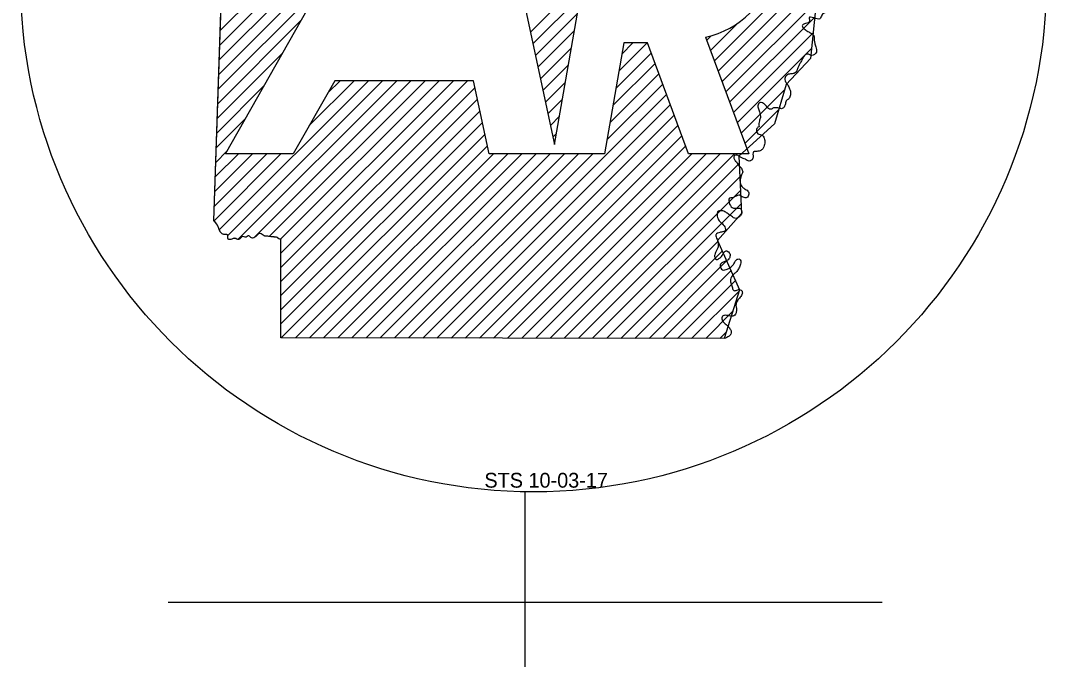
# Model space of a CAD drawing. Extents: x 1373094 to 1376427, y 1168361 to 1170494.
# Drawn here: x 1374019.33 to 1374059.68, y 1169704 to 1169729.15 of the extents above; entities that cross this region are included whole.
import ezdxf

# ---------------------------------------------------------------- set-up
doc = ezdxf.new("R2010")
doc.units = 0
doc.layers.add('R_Draft', color=7, linetype='Continuous')
doc.layers.add('R_Water Annot', color=7, linetype='Continuous')

msp = doc.modelspace()

# ---------------------------------------------------------------- linework, layer by layer
at = {"layer": 'R_Draft'}
for p, q in [((1374027.385, 1169723.893), (1374035.162, 1169737.628)), ((1374043.988, 1169728.261), (1374043.052, 1169728.261)), ((1374045.602, 1169723.893), (1374043.988, 1169728.261)), ((1374046.274, 1169728.495), (1374047.974, 1169723.893)), ((1374031.686, 1169726.775), (1374030.054, 1169723.893)), ((1374037.148, 1169726.775), (1374031.686, 1169726.775)), ((1374030.054, 1169723.893), (1374027.385, 1169723.893)), ((1374042.291, 1169723.893), (1374037.765, 1169723.893)), ((1374047.974, 1169723.893), (1374045.602, 1169723.893)), ((1374039.178, 1169659.407), (1374039.178, 1169710.597)), ((1374025.136, 1169706.246), (1374053.217, 1169706.246))]:
    msp.add_line(p, q, dxfattribs=at)
for points in [[(1374026.933, 1169721.272), (1374027.361, 1169734.176), (1374026.377, 1169742.081)], [(1374054.888, 1169738.766), (1374055.553, 1169738.071), (1374053.894, 1169736.707), (1374054.073, 1169735.33), (1374052.65, 1169734.392), (1374053.137, 1169732.274), (1374052.04, 1169731.274), (1374051.942, 1169730.185), (1374050.608, 1169729.705), (1374050.401, 1169727.653), (1374049.442, 1169726.626), (1374048.979, 1169725.08), (1374047.583, 1169723.803), (1374047.689, 1169721.548), (1374046.74, 1169720.485), (1374047.604, 1169718.551), (1374047.006, 1169716.629)], [(1374037.473, 1169737.628), (1374040.334, 1169724.261), (1374042.164, 1169734.763)], [(1374026.935, 1169721.27), (1374027.227, 1169730.125)], [(1374043.052, 1169728.261), (1374042.291, 1169723.893)], [(1374037.765, 1169723.893), (1374037.148, 1169726.775)], [(1374047.006, 1169716.629), (1374029.573, 1169716.658), (1374029.564, 1169720.506)], [(1374047.005, 1169716.627), (1374029.573, 1169716.658), (1374029.566, 1169720.507)]]:
    msp.add_lwpolyline(points, dxfattribs=at)
msp.add_ellipse((1374039.504, 1169730.77), major_axis=(20.176, 0), ratio=0.999976, dxfattribs=at)
msp.add_ellipse((1374045.557, 1169731.909), major_axis=(-3.489, 0), ratio=0.999987, start_param=1.777838, end_param=4.099264, dxfattribs=at)
for points in [[(1374051.01, 1169729.476), (1374050.845, 1169729.35), (1374050.77, 1169729.218), (1374050.347, 1169729.256), (1374050.358, 1169729.108), (1374050.208, 1169729.03), (1374050.074, 1169728.933), (1374050.15, 1169728.818), (1374050.294, 1169728.714), (1374050.436, 1169728.634), (1374050.525, 1169728.554), (1374050.549, 1169728.355), (1374050.575, 1169728.233), (1374050.622, 1169728.06), (1374050.64, 1169727.944), (1374050.554, 1169727.803), (1374050.454, 1169727.772), (1374050.351, 1169727.806), (1374050.228, 1169727.815), (1374050.128, 1169727.722), (1374050.056, 1169727.587), (1374049.986, 1169727.451), (1374049.932, 1169727.339), (1374049.876, 1169727.214), (1374049.776, 1169727.07), (1374049.649, 1169727.05), (1374049.495, 1169727.011), (1374049.404, 1169726.909), (1374049.42, 1169726.731), (1374049.505, 1169726.613), (1374049.571, 1169726.463), (1374049.616, 1169726.336), (1374049.597, 1169726.175), (1374049.53, 1169726.053), (1374049.443, 1169725.982), (1374049.404, 1169725.832), (1374049.341, 1169725.715), (1374049.286, 1169725.68), (1374049.172, 1169725.691), (1374049.049, 1169725.713), (1374048.944, 1169725.704), (1374048.845, 1169725.651), (1374048.743, 1169725.685), (1374048.639, 1169725.798), (1374048.553, 1169725.884), (1374048.457, 1169725.918), (1374048.355, 1169725.866), (1374048.341, 1169725.707), (1374048.389, 1169725.548), (1374048.43, 1169725.327), (1374048.389, 1169725.196), (1374048.374, 1169724.973)], [(1374048.374, 1169724.973), (1374048.361, 1169724.967), (1374048.277, 1169724.86), (1374048.323, 1169724.691), (1374048.509, 1169724.626), (1374048.594, 1169724.465), (1374048.598, 1169724.323), (1374048.539, 1169724.127), (1374048.451, 1169724.035), (1374048.286, 1169723.996), (1374048.159, 1169723.974), (1374048.14, 1169723.755), (1374048.08, 1169723.646), (1374047.982, 1169723.613), (1374047.838, 1169723.683), (1374047.752, 1169723.72), (1374047.648, 1169723.767), (1374047.515, 1169723.842), (1374047.413, 1169723.829), (1374047.442, 1169723.622), (1374047.452, 1169723.613), (1374047.567, 1169723.455), (1374047.679, 1169723.331), (1374047.732, 1169723.184)], [(1374048.374, 1169724.973), (1374048.361, 1169724.967), (1374048.277, 1169724.86), (1374048.323, 1169724.691), (1374048.509, 1169724.626), (1374048.594, 1169724.465), (1374048.598, 1169724.323), (1374048.539, 1169724.127), (1374048.451, 1169724.035), (1374048.286, 1169723.996), (1374048.159, 1169723.974), (1374048.14, 1169723.755), (1374048.08, 1169723.646), (1374047.982, 1169723.613), (1374047.838, 1169723.683), (1374047.752, 1169723.72), (1374047.648, 1169723.767), (1374047.515, 1169723.842), (1374047.413, 1169723.829), (1374047.442, 1169723.622), (1374047.452, 1169723.613), (1374047.567, 1169723.455), (1374047.679, 1169723.331), (1374047.732, 1169723.184)], [(1374047.732, 1169723.184), (1374047.687, 1169723.073), (1374047.632, 1169722.884), (1374047.648, 1169722.724), (1374047.721, 1169722.586), (1374047.833, 1169722.51), (1374047.959, 1169722.401), (1374047.948, 1169722.232), (1374047.875, 1169722.173), (1374047.707, 1169722.212), (1374047.579, 1169722.273), (1374047.472, 1169722.238), (1374047.327, 1169722.167), (1374047.215, 1169722.148), (1374047.22, 1169721.922), (1374047.365, 1169721.761), (1374047.494, 1169721.761), (1374047.645, 1169721.743), (1374047.696, 1169721.572), (1374047.609, 1169721.427), (1374047.468, 1169721.358), (1374047.287, 1169721.445), (1374047.159, 1169721.534), (1374047.03, 1169721.619), (1374046.869, 1169721.661), (1374046.777, 1169721.644), (1374046.734, 1169721.445), (1374046.811, 1169721.263), (1374046.933, 1169721.137), (1374047.047, 1169720.978), (1374047.03, 1169720.856), (1374046.944, 1169720.825), (1374046.791, 1169720.791), (1374046.702, 1169720.745), (1374046.679, 1169720.707), (1374046.726, 1169720.544), (1374046.767, 1169720.37), (1374046.767, 1169720.233), (1374046.715, 1169720.114), (1374046.634, 1169719.924), (1374046.644, 1169719.801), (1374046.702, 1169719.74), (1374046.772, 1169719.759), (1374046.869, 1169719.825), (1374046.93, 1169719.902), (1374046.984, 1169719.998), (1374047.081, 1169720.077), (1374047.204, 1169720.006), (1374047.233, 1169719.859), (1374047.162, 1169719.732), (1374047.062, 1169719.672), (1374046.941, 1169719.624), (1374046.849, 1169719.522), (1374046.871, 1169719.396), (1374046.944, 1169719.33), (1374047.122, 1169719.365), (1374047.237, 1169719.418), (1374047.307, 1169719.48), (1374047.387, 1169719.563), (1374047.427, 1169719.647), (1374047.491, 1169719.732), (1374047.602, 1169719.755), (1374047.654, 1169719.685), (1374047.632, 1169719.522), (1374047.567, 1169719.367), (1374047.475, 1169719.241), (1374047.377, 1169719.152), (1374047.253, 1169718.956), (1374047.278, 1169718.776), (1374047.327, 1169718.624), (1374047.388, 1169718.513), (1374047.505, 1169718.536), (1374047.632, 1169718.551), (1374047.707, 1169718.49), (1374047.701, 1169718.356), (1374047.606, 1169718.224), (1374047.515, 1169718.103), (1374047.468, 1169717.934), (1374047.487, 1169717.812), (1374047.487, 1169717.707), (1374047.449, 1169717.584), (1374047.383, 1169717.518), (1374047.204, 1169717.52), (1374047.02, 1169717.541), (1374046.921, 1169717.485), (1374046.941, 1169717.324), (1374047.047, 1169717.204), (1374047.123, 1169717.144), (1374047.233, 1169717.01), (1374047.281, 1169716.901), (1374047.267, 1169716.805), (1374047.198, 1169716.721), (1374047.005, 1169716.627)], [(1374047.732, 1169723.184), (1374047.687, 1169723.073), (1374047.632, 1169722.884), (1374047.648, 1169722.724), (1374047.721, 1169722.586), (1374047.833, 1169722.51), (1374047.959, 1169722.401), (1374047.948, 1169722.232), (1374047.875, 1169722.173), (1374047.707, 1169722.212), (1374047.579, 1169722.273), (1374047.472, 1169722.238), (1374047.327, 1169722.167), (1374047.215, 1169722.148), (1374047.22, 1169721.922), (1374047.365, 1169721.761), (1374047.494, 1169721.761), (1374047.645, 1169721.743), (1374047.696, 1169721.572), (1374047.609, 1169721.427), (1374047.468, 1169721.358), (1374047.287, 1169721.445), (1374047.159, 1169721.534), (1374047.03, 1169721.619), (1374046.869, 1169721.661), (1374046.777, 1169721.644), (1374046.734, 1169721.445), (1374046.811, 1169721.263), (1374046.933, 1169721.137), (1374047.047, 1169720.978), (1374047.03, 1169720.856), (1374046.944, 1169720.825), (1374046.791, 1169720.791), (1374046.702, 1169720.745), (1374046.679, 1169720.707), (1374046.726, 1169720.544), (1374046.767, 1169720.37), (1374046.767, 1169720.233), (1374046.715, 1169720.114), (1374046.634, 1169719.924), (1374046.644, 1169719.801), (1374046.702, 1169719.74), (1374046.772, 1169719.759), (1374046.869, 1169719.825), (1374046.93, 1169719.902), (1374046.984, 1169719.998), (1374047.081, 1169720.077), (1374047.204, 1169720.006), (1374047.233, 1169719.859), (1374047.162, 1169719.732), (1374047.062, 1169719.672), (1374046.941, 1169719.624), (1374046.849, 1169719.522), (1374046.871, 1169719.396), (1374046.944, 1169719.33), (1374047.122, 1169719.365), (1374047.237, 1169719.418), (1374047.307, 1169719.48), (1374047.387, 1169719.563), (1374047.427, 1169719.647), (1374047.491, 1169719.732), (1374047.602, 1169719.755), (1374047.654, 1169719.685), (1374047.632, 1169719.522), (1374047.567, 1169719.367), (1374047.475, 1169719.241), (1374047.377, 1169719.152), (1374047.253, 1169718.956), (1374047.278, 1169718.776), (1374047.327, 1169718.624), (1374047.388, 1169718.513), (1374047.505, 1169718.536), (1374047.632, 1169718.551), (1374047.707, 1169718.49), (1374047.701, 1169718.356), (1374047.606, 1169718.224), (1374047.515, 1169718.103), (1374047.468, 1169717.934), (1374047.487, 1169717.812), (1374047.487, 1169717.707), (1374047.449, 1169717.584), (1374047.383, 1169717.518), (1374047.204, 1169717.52), (1374047.02, 1169717.541), (1374046.921, 1169717.485), (1374046.941, 1169717.324), (1374047.047, 1169717.204), (1374047.123, 1169717.144), (1374047.233, 1169717.01), (1374047.281, 1169716.901), (1374047.267, 1169716.805), (1374047.198, 1169716.721), (1374047.005, 1169716.627)], [(1374029.564, 1169720.506), (1374029.583, 1169720.496), (1374029.492, 1169720.558), (1374029.369, 1169720.62), (1374029.231, 1169720.63), (1374029.055, 1169720.653), (1374028.907, 1169720.668), (1374028.755, 1169720.767), (1374028.593, 1169720.663), (1374028.413, 1169720.587), (1374028.308, 1169720.672), (1374028.17, 1169720.615), (1374028.075, 1169720.644), (1374027.908, 1169720.53), (1374027.751, 1169720.572), (1374027.637, 1169720.539), (1374027.495, 1169720.544), (1374027.466, 1169720.706), (1374027.328, 1169720.729), (1374027.209, 1169720.796), (1374027.128, 1169720.963), (1374027.071, 1169721.091), (1374026.933, 1169721.272)], [(1374029.566, 1169720.507), (1374029.584, 1169720.497), (1374029.494, 1169720.559), (1374029.369, 1169720.619), (1374029.229, 1169720.628), (1374029.053, 1169720.652), (1374028.906, 1169720.666), (1374028.756, 1169720.767), (1374028.595, 1169720.665), (1374028.413, 1169720.586), (1374028.308, 1169720.675), (1374028.172, 1169720.614), (1374028.075, 1169720.646), (1374027.909, 1169720.529), (1374027.75, 1169720.573), (1374027.638, 1169720.541), (1374027.496, 1169720.544), (1374027.466, 1169720.707), (1374027.327, 1169720.728), (1374027.208, 1169720.796), (1374027.129, 1169720.961), (1374027.07, 1169721.093), (1374026.935, 1169721.27)]]:
    msp.add_spline(points, degree=3, dxfattribs=at)
at = {"layer": 'R_Water Annot'}
for p, q in [((1374027.181, 1169728.753), (1374033.996, 1169735.567)), ((1374027.162, 1169728.176), (1374033.268, 1169734.282)), ((1374046.619, 1169727.563), (1374052.799, 1169733.743)), ((1374046.769, 1169727.156), (1374052.904, 1169733.29)), ((1374027.143, 1169727.6), (1374032.54, 1169732.997)), ((1374046.92, 1169726.748), (1374053.008, 1169732.837)), ((1374047.07, 1169726.341), (1374053.112, 1169732.383)), ((1374027.124, 1169727.023), (1374031.812, 1169731.711)), ((1374039.386, 1169728.692), (1374041.47, 1169730.776)), ((1374027.105, 1169726.447), (1374031.084, 1169730.426)), ((1374039.484, 1169728.233), (1374041.352, 1169730.101)), ((1374027.086, 1169725.87), (1374030.357, 1169729.141)), ((1374039.582, 1169727.774), (1374041.234, 1169729.426)), ((1374047.22, 1169725.934), (1374050.565, 1169729.279)), ((1374039.681, 1169727.314), (1374041.117, 1169728.75)), ((1374046.468, 1169727.97), (1374047.529, 1169729.031)), ((1374047.371, 1169725.527), (1374050.502, 1169728.659)), ((1374042.858, 1169727.147), (1374043.973, 1169728.261)), ((1374042.976, 1169727.822), (1374043.415, 1169728.261)), ((1374046.318, 1169728.377), (1374046.487, 1169728.546)), ((1374027.067, 1169725.293), (1374029.629, 1169727.855)), ((1374039.779, 1169726.855), (1374040.999, 1169728.075)), ((1374042.741, 1169726.472), (1374044.134, 1169727.866)), ((1374047.521, 1169725.12), (1374050.44, 1169728.038)), ((1374042.623, 1169725.797), (1374044.285, 1169727.459)), ((1374039.877, 1169726.396), (1374040.881, 1169727.4)), ((1374042.505, 1169725.122), (1374044.435, 1169727.052)), ((1374027.149, 1169720.916), (1374033.009, 1169726.775)), ((1374027.481, 1169720.69), (1374033.566, 1169726.775)), ((1374027.881, 1169720.533), (1374034.124, 1169726.775)), ((1374028.543, 1169720.637), (1374034.681, 1169726.775)), ((1374029.109, 1169720.646), (1374035.239, 1169726.775)), ((1374029.546, 1169720.525), (1374035.796, 1169726.775)), ((1374029.565, 1169719.987), (1374036.354, 1169726.775)), ((1374029.566, 1169719.43), (1374036.911, 1169726.775)), ((1374030.686, 1169725.01), (1374032.451, 1169726.775)), ((1374031.414, 1169726.296), (1374031.894, 1169726.775)), ((1374039.975, 1169725.937), (1374040.764, 1169726.725)), ((1374042.388, 1169724.447), (1374044.586, 1169726.645)), ((1374027.048, 1169724.717), (1374028.901, 1169726.57)), ((1374029.568, 1169718.874), (1374037.205, 1169726.511)), ((1374035.147, 1169716.649), (1374044.736, 1169726.237)), ((1374047.672, 1169724.713), (1374049.381, 1169726.422)), ((1374029.569, 1169718.318), (1374037.303, 1169726.052)), ((1374035.704, 1169716.648), (1374044.886, 1169725.83)), ((1374040.074, 1169725.478), (1374040.646, 1169726.05)), ((1374029.57, 1169717.762), (1374037.401, 1169725.593)), ((1374047.822, 1169724.306), (1374049.143, 1169725.626)), ((1374027.028, 1169724.14), (1374028.173, 1169725.285)), ((1374029.572, 1169717.206), (1374037.5, 1169725.134)), ((1374036.26, 1169716.647), (1374045.037, 1169725.423)), ((1374040.172, 1169725.018), (1374040.528, 1169725.375)), ((1374029.581, 1169716.658), (1374037.598, 1169724.674)), ((1374036.817, 1169716.646), (1374045.187, 1169725.016)), ((1374040.27, 1169724.559), (1374040.411, 1169724.699)), ((1374030.138, 1169716.657), (1374037.696, 1169724.215)), ((1374037.374, 1169716.645), (1374045.338, 1169724.609)), ((1374026.941, 1169721.266), (1374029.569, 1169723.893)), ((1374026.952, 1169721.834), (1374029.012, 1169723.893)), ((1374026.971, 1169722.41), (1374028.454, 1169723.893)), ((1374026.99, 1169722.987), (1374027.897, 1169723.893)), ((1374027.009, 1169723.563), (1374027.446, 1169724)), ((1374030.694, 1169716.656), (1374037.932, 1169723.893)), ((1374031.251, 1169716.655), (1374038.489, 1169723.893)), ((1374031.808, 1169716.654), (1374039.047, 1169723.893)), ((1374032.364, 1169716.653), (1374039.604, 1169723.893)), ((1374032.921, 1169716.652), (1374040.162, 1169723.893)), ((1374033.477, 1169716.651), (1374040.719, 1169723.893)), ((1374034.034, 1169716.651), (1374041.277, 1169723.893)), ((1374034.591, 1169716.65), (1374041.834, 1169723.893)), ((1374037.93, 1169716.644), (1374045.488, 1169724.202)), ((1374038.487, 1169716.643), (1374045.737, 1169723.893)), ((1374039.043, 1169716.642), (1374046.295, 1169723.893)), ((1374039.6, 1169716.641), (1374046.852, 1169723.893)), ((1374040.157, 1169716.641), (1374047.41, 1169723.893)), ((1374040.713, 1169716.64), (1374047.596, 1169723.522)), ((1374041.27, 1169716.639), (1374047.621, 1169722.99)), ((1374041.826, 1169716.638), (1374047.646, 1169722.457)), ((1374042.383, 1169716.637), (1374047.671, 1169721.925)), ((1374042.94, 1169716.636), (1374046.755, 1169720.452)), ((1374043.496, 1169716.635), (1374046.927, 1169720.066)), ((1374044.053, 1169716.634), (1374047.1, 1169719.681)), ((1374044.609, 1169716.633), (1374047.272, 1169719.296)), ((1374045.166, 1169716.632), (1374047.444, 1169718.91)), ((1374045.722, 1169716.631), (1374047.588, 1169718.497)), ((1374046.279, 1169716.631), (1374047.335, 1169717.687)), ((1374046.836, 1169716.63), (1374047.083, 1169716.877))]:
    msp.add_line(p, q, dxfattribs=at)

# ---------------------------------------------------------------- texts
at = {"layer": 'R_Draft'}
msp.add_text('STS 10-03-17', height=0.58333, dxfattribs=at).set_placement((1374037.574, 1169710.759))

doc.saveas('drawing.dxf')
